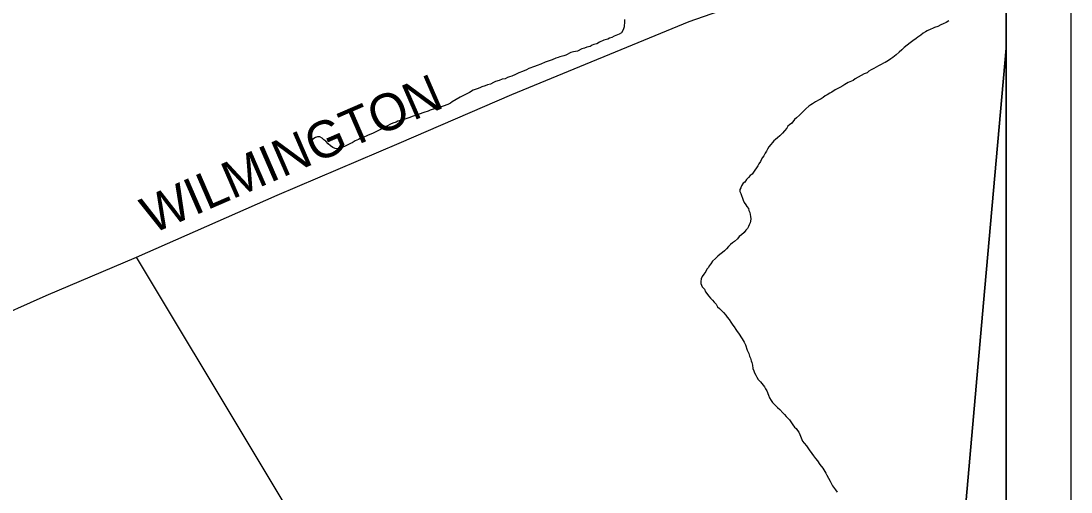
# Model space of a CAD drawing. Extents: x 0.4 to 34.4, y -2.1 to 19.9.
# Drawn here: x 8.281 to 9.9, y 14.658 to 15.384 of the extents above; entities that cross this region are included whole.
import ezdxf

# ---------------------------------------------------------------- set-up
doc = ezdxf.new("R2010")
doc.units = 0
for name, color, linetype in [('GM_X_Adjacent_County', 7, 'Continuous'), ('GM_X_County', 7, 'Continuous'), ('GM_X_County_Road', 7, 'Continuous'), ('GM_X_County_Road_Text', 7, 'Continuous'), ('GM_X_Minor_River', 7, 'Continuous'), ('GM_X_Township', 7, 'Continuous'), ('SH_Data', 7, 'Continuous')]:
    doc.layers.add(name, color=color, linetype=linetype)

msp = doc.modelspace()

# ---------------------------------------------------------------- linework, layer by layer
at = {"layer": 'GM_X_Adjacent_County'}
for points in [[(9.5074, 12.0357), (9.8001, 12.0357), (9.8001, 15.3423)], [(9.8001, 15.3423), (9.7654, 14.9495), (9.706, 14.2776), (9.6797, 13.9803), (9.6042, 13.1277), (9.5589, 12.6168), (9.5074, 12.0357)]]:
    msp.add_lwpolyline(points, dxfattribs=at)
at = {"layer": 'GM_X_County'}
for points in [[(9.8001, 15.3423), (9.8001, 18.8357), (3.0001, 18.8357), (3.0001, 12.0357), (9.5074, 12.0357)], [(9.5074, 12.0357), (9.5589, 12.6168), (9.6042, 13.1277), (9.6797, 13.9803), (9.706, 14.2776), (9.7654, 14.9495), (9.8001, 15.3423)]]:
    msp.add_lwpolyline(points, dxfattribs=at)
at = {"layer": 'GM_X_County_Road'}
for points in [[(8.2275, 14.9194), (8.32, 14.9606), (8.4596, 15.0199), (8.6764, 15.1154), (8.8642, 15.1959), (9.0381, 15.2705), (9.3113, 15.3835), (9.4976, 15.4487), (9.5613, 15.4693), (9.8001, 15.5501)], [(9.2621, 13.6921), (9.2169, 13.7627), (9.1648, 13.8442), (8.4596, 15.0199)]]:
    msp.add_lwpolyline(points, dxfattribs=at)
at = {"layer": 'GM_X_Minor_River'}
for points in [[(9.2117, 15.3863), (9.2116, 15.3836), (9.2116, 15.3806), (9.2111, 15.3775), (9.2111, 15.3749)], [(9.7117, 15.3843), (9.7078, 15.3817), (9.7033, 15.3799), (9.6994, 15.3784), (9.6948, 15.3758), (9.6895, 15.374), (9.6868, 15.3725), (9.6842, 15.3714), (9.6784, 15.3688), (9.6757, 15.3674), (9.6723, 15.3651), (9.6685, 15.3621), (9.6642, 15.3592), (9.6612, 15.3569), (9.6562, 15.3536), (9.652, 15.3502), (9.6474, 15.3469), (9.6427, 15.3431), (9.6393, 15.3398), (9.6351, 15.336), (9.6304, 15.3319), (9.6254, 15.3278), (9.6224, 15.3256), (9.6189, 15.3233), (9.6136, 15.32), (9.6109, 15.3189), (9.6074, 15.317), (9.6032, 15.3148), (9.5998, 15.313), (9.5964, 15.3111), (9.5921, 15.3089), (9.5887, 15.3067), (9.586, 15.3044), (9.5814, 15.3026), (9.5768, 15.3), (9.5719, 15.2974), (9.5673, 15.2948), (9.5642, 15.2922), (9.5566, 15.2893), (9.5516, 15.2863), (9.5485, 15.2841), (9.5439, 15.2815), (9.5367, 15.2778), (9.5313, 15.2744), (9.5282, 15.2726), (9.524, 15.2704), (9.521, 15.2685), (9.5179, 15.2659), (9.5152, 15.264), (9.5118, 15.2626), (9.5064, 15.2596), (9.5018, 15.2566), (9.4991, 15.2547), (9.4961, 15.2529), (9.4914, 15.2488), (9.4884, 15.2454), (9.4849, 15.242), (9.4814, 15.239), (9.4768, 15.2346), (9.4741, 15.2323), (9.4695, 15.2267), (9.466, 15.2241), (9.4634, 15.2218), (9.4618, 15.2188), (9.4583, 15.2147), (9.4552, 15.2113), (9.4514, 15.2068), (9.4475, 15.2038), (9.4448, 15.2016), (9.4422, 15.1993), (9.4402, 15.1967), (9.4375, 15.1937), (9.4344, 15.1899), (9.4321, 15.1866), (9.4305, 15.1832), (9.4286, 15.1801), (9.4266, 15.1764)], [(9.2111, 15.3749), (9.2102, 15.3719), (9.209, 15.3692), (9.207, 15.3658), (9.2036, 15.364), (9.1986, 15.3618), (9.1959, 15.3607), (9.1924, 15.3589), (9.1885, 15.3574), (9.1859, 15.3563), (9.1797, 15.3545), (9.1732, 15.3516), (9.1693, 15.349), (9.1647, 15.3479), (9.162, 15.3469), (9.1589, 15.345), (9.1539, 15.3436), (9.1501, 15.3421), (9.1462, 15.3411), (9.1393, 15.3378), (9.1332, 15.3363), (9.129, 15.3353), (9.1213, 15.3316), (9.1182, 15.3305), (9.112, 15.3287), (9.1093, 15.3276), (9.1059, 15.327), (9.1001, 15.324), (9.094, 15.3222), (9.0897, 15.3208), (9.0828, 15.3175), (9.0771, 15.3157), (9.0732, 15.3138), (9.0644, 15.311), (9.0609, 15.3087), (9.0547, 15.3062), (9.049, 15.3044), (9.0436, 15.3018), (9.0382, 15.2989), (9.0343, 15.2982), (9.0313, 15.2971), (9.0278, 15.2949), (9.0232, 15.2942), (9.0186, 15.2924), (9.0128, 15.2906), (9.0097, 15.2891), (9.0051, 15.2869), (9.0005, 15.2859), (8.997, 15.284), (8.9921, 15.2826), (8.9886, 15.2811), (8.9847, 15.2797), (8.9817, 15.2786), (8.9786, 15.2775), (8.9728, 15.2738), (8.9666, 15.2705), (8.9628, 15.2687), (8.9585, 15.2665), (8.9524, 15.2632), (8.9462, 15.2595), (8.9435, 15.2572), (8.9392, 15.2554), (8.9323, 15.2525), (8.9277, 15.2514), (8.9246, 15.2503), (8.9204, 15.2489), (8.9123, 15.2464), (8.9092, 15.2449), (8.9023, 15.2428), (8.8954, 15.2406), (8.8912, 15.2388), (8.8847, 15.237), (8.8808, 15.2352), (8.8701, 15.2319), (8.8624, 15.2294), (8.8597, 15.2283), (8.8547, 15.2265), (8.8512, 15.225), (8.8454, 15.2221), (8.8377, 15.2177), (8.8304, 15.214), (8.8273, 15.2125), (8.8242, 15.2111), (8.8208, 15.2096), (8.8165, 15.2078), (8.8135, 15.2067), (8.8108, 15.2056), (8.8069, 15.2042), (8.8019, 15.2016), (8.7992, 15.2005), (8.7965, 15.1994), (8.7919, 15.1964), (8.7892, 15.1954), (8.7865, 15.1935), (8.783, 15.192), (8.7803, 15.1906), (8.7761, 15.1891), (8.7726, 15.188), (8.7692, 15.187), (8.7658, 15.1874), (8.7624, 15.189)], [(8.7624, 15.189), (8.7586, 15.1917), (8.7552, 15.1948), (8.7515, 15.1987), (8.7485, 15.201), (8.7459, 15.2034), (8.7421, 15.2053), (8.7387, 15.2054), (8.7353, 15.2043), (8.7326, 15.2029), (8.7298, 15.2002)], [(9.4266, 15.1764), (9.4247, 15.1734), (9.4224, 15.17), (9.4212, 15.1673), (9.4189, 15.164), (9.4173, 15.1609), (9.4154, 15.1579), (9.4127, 15.1542), (9.4107, 15.1512), (9.4084, 15.1481), (9.4057, 15.1459), (9.403, 15.1425), (9.3999, 15.1395), (9.3972, 15.1358), (9.3945, 15.1339), (9.3922, 15.1298), (9.391, 15.1267), (9.3898, 15.1241), (9.3898, 15.1211), (9.3909, 15.118), (9.392, 15.1149), (9.3935, 15.1107), (9.3946, 15.1077), (9.3964, 15.1043), (9.3986, 15.1008), (9.4005, 15.0981), (9.4027, 15.0947), (9.4034, 15.092), (9.4049, 15.0886), (9.4053, 15.0859), (9.406, 15.0828), (9.4063, 15.079), (9.4059, 15.0756), (9.4055, 15.073), (9.4039, 15.07), (9.4031, 15.0673), (9.4012, 15.0643), (9.3988, 15.0613), (9.3961, 15.0579), (9.3923, 15.0542), (9.3885, 15.0516), (9.3858, 15.0482), (9.3815, 15.0441), (9.3785, 15.0422), (9.3754, 15.0392), (9.3719, 15.0362), (9.3692, 15.0328), (9.3661, 15.0298), (9.3627, 15.0272), (9.3588, 15.0239), (9.3558, 15.0216), (9.3523, 15.0179), (9.3477, 15.0138), (9.345, 15.0096), (9.3423, 15.0066), (9.3415, 15.004), (9.3388, 15.0014), (9.3372, 14.998), (9.3341, 14.9938), (9.3314, 14.9901), (9.3298, 14.9863), (9.3294, 14.9825), (9.3297, 14.9791), (9.3316, 14.9741), (9.3349, 14.9703), (9.3368, 14.9664), (9.342, 14.9599), (9.3442, 14.9565), (9.3472, 14.9534), (9.3498, 14.9503), (9.3532, 14.9472), (9.3551, 14.9434), (9.3581, 14.9407), (9.3607, 14.9384), (9.3644, 14.9345), (9.3678, 14.9303), (9.37, 14.9276), (9.373, 14.9238), (9.3756, 14.9196), (9.379, 14.9149), (9.3808, 14.9123), (9.3834, 14.9084), (9.3853, 14.9054), (9.3875, 14.9027), (9.3894, 14.8996), (9.3912, 14.8969), (9.3931, 14.8939), (9.3964, 14.8889), (9.3983, 14.8847), (9.4008, 14.8763), (9.4034, 14.8713), (9.4045, 14.8671), (9.406, 14.864), (9.4071, 14.8602), (9.4082, 14.8572), (9.4089, 14.8534), (9.4096, 14.8484), (9.411, 14.8446), (9.4121, 14.8415), (9.414, 14.8381), (9.4158, 14.835)], [(9.4158, 14.835), (9.418, 14.8312), (9.4214, 14.8274), (9.4255, 14.8227), (9.4274, 14.8201), (9.4292, 14.817), (9.4311, 14.8136), (9.4337, 14.8071), (9.4355, 14.8029), (9.4377, 14.799), (9.44, 14.7956), (9.4437, 14.7921), (9.4474, 14.7879), (9.4512, 14.7848), (9.4557, 14.7798), (9.4583, 14.7775), (9.4609, 14.774), (9.4635, 14.7717), (9.4662, 14.769), (9.4691, 14.7644), (9.4714, 14.7613), (9.474, 14.7575), (9.4766, 14.7556), (9.4785, 14.7525), (9.4803, 14.7498), (9.4822, 14.7464), (9.4862, 14.7361), (9.4888, 14.733), (9.4922, 14.7291), (9.4967, 14.723), (9.5008, 14.7169), (9.503, 14.7134), (9.506, 14.7096), (9.5093, 14.7057), (9.5131, 14.7003), (9.5175, 14.6946), (9.5205, 14.6896), (9.522, 14.6869), (9.5235, 14.6839), (9.5261, 14.6793), (9.5286, 14.6743), (9.5305, 14.6712), (9.5327, 14.6674), (9.5372, 14.6613), (9.5394, 14.6574)]]:
    msp.add_lwpolyline(points, dxfattribs=at)
at = {"layer": 'GM_X_Township'}
msp.add_line((9.8001, 15.3423), (9.8001, 15.535), dxfattribs=at)
msp.add_lwpolyline([(9.5074, 12.0357), (9.5589, 12.6168), (9.6042, 13.1277), (9.6797, 13.9803), (9.706, 14.2776), (9.7654, 14.9495), (9.8001, 15.3423)], dxfattribs=at)
at = {"layer": 'SH_Data'}
for p, q in [((9.9001, 18.9357), (9.9001, 11.9357)), ((9.8001, 18.8357), (9.8001, 12.0357))]:
    msp.add_line(p, q, dxfattribs=at)

# ---------------------------------------------------------------- texts
at = {"layer": 'GM_X_County_Road_Text'}
msp.add_text('WILMINGTON', height=0.05682, rotation=23.4575, dxfattribs=at).set_placement((8.483, 15.0551))

doc.saveas('drawing.dxf')
